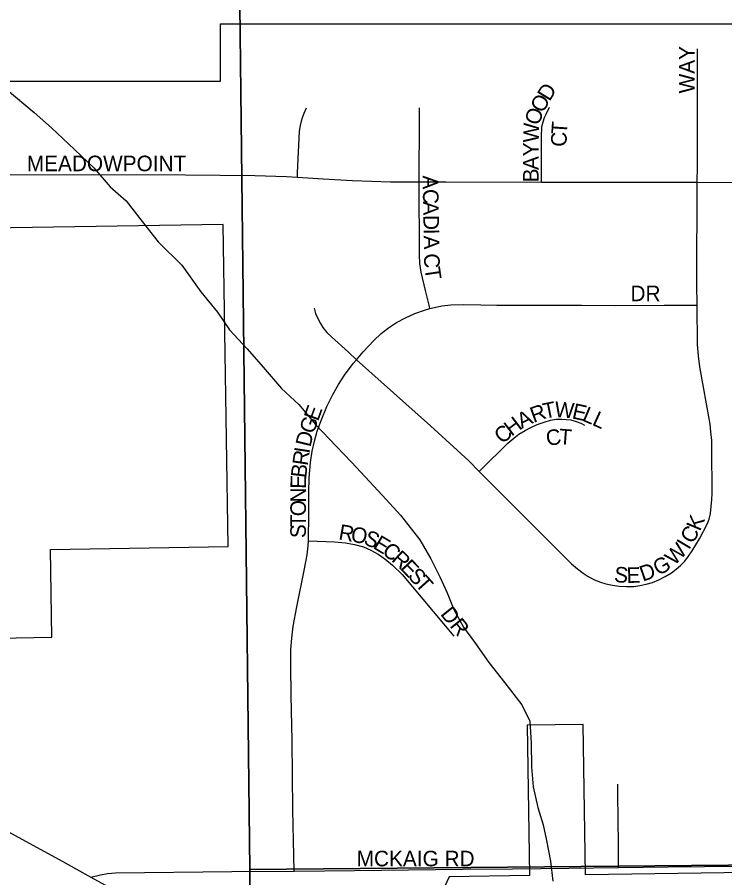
# Model space of a CAD drawing. Extents: x 0 to 680, y 0 to 440.
# Drawn here: x 433.41 to 441, y 330.74 to 339.97 of the extents above; entities that cross this region are included whole.
import ezdxf

# ---------------------------------------------------------------- set-up
doc = ezdxf.new("R2010")
doc.units = 0
for name, color, linetype in [('GM_X_City_Street', 7, 'Continuous'), ('GM_X_City_Street_Text', 7, 'Continuous'), ('GM_X_Corporation', 7, 'Continuous'), ('GM_X_County_Road', 7, 'Continuous'), ('GM_X_Minor_River', 7, 'Continuous'), ('GM_X_Section', 7, 'Continuous'), ('GM_X_State_Route', 7, 'Continuous')]:
    doc.layers.add(name, color=color, linetype=linetype)

msp = doc.modelspace()

# ---------------------------------------------------------------- linework, layer by layer
at = {"layer": 'GM_X_City_Street'}
for points in [[(440.7016, 338.1998), (440.7023, 338.3733), (440.7039, 339.1836), (440.7049, 339.6327)], [(436.411, 338.2539), (436.4132, 338.3002), (436.4344, 338.7505), (436.4431, 338.8091), (436.4639, 338.8851), (436.4846, 338.9427), (436.5098, 338.9997)], [(437.7185, 338.2041), (437.7182, 338.3199), (437.7207, 338.7769), (437.7219, 338.9986)], [(439.0301, 338.2029), (439.0301, 338.2146), (439.0305, 338.7275), (439.0325, 338.7598), (439.0343, 338.7904), (439.0409, 338.8235), (439.0486, 338.8508), (439.0639, 338.8941), (439.0792, 338.9298), (439.1171, 339.0069)], [(432.655, 338.2766), (432.6772, 338.2768), (433.3471, 338.2832), (435.2091, 338.2798), (435.9544, 338.2721), (436.2932, 338.2616), (436.411, 338.2539)], [(436.411, 338.2539), (436.6875, 338.2358), (437.0016, 338.2203), (437.4092, 338.2044), (437.7185, 338.2041)], [(437.8321, 336.8438), (437.8235, 336.88), (437.7854, 337.0397), (437.7382, 337.2373), (437.725, 337.328), (437.7204, 337.4221), (437.7185, 338.2041)], [(437.7185, 338.2041), (438.0055, 338.2038), (439.0301, 338.2029)], [(439.0301, 338.2029), (439.1397, 338.2028), (440.2238, 338.2008), (440.7016, 338.1998)], [(440.6995, 336.8821), (440.6977, 337.1031), (440.7016, 338.1998)], [(440.7016, 338.1998), (441.4396, 338.1982), (441.6928, 338.1889), (441.7558, 338.1827), (441.8128, 338.1712), (441.8745, 338.1537)], [(437.8321, 336.8438), (437.8828, 336.858), (437.9592, 336.873), (438.0585, 336.8837), (438.1909, 336.8884), (438.3775, 336.8844), (438.5524, 336.8817), (439.0009, 336.8805), (439.4609, 336.8806), (439.822, 336.8778), (440.3474, 336.8806), (440.5663, 336.8816), (440.6995, 336.8821)], [(438.3622, 335.0968), (439.3519, 334.1055), (439.4162, 334.0509), (439.4783, 334.0039), (439.5304, 333.9695), (439.5908, 333.9366), (439.6511, 333.913), (439.7204, 333.8904), (439.7903, 333.8776), (439.8634, 333.8669), (439.9409, 333.861), (440.0194, 333.8627), (440.0842, 333.871), (440.1518, 333.8856), (440.2208, 333.9064), (440.288, 333.9349), (440.3559, 333.9695), (440.4246, 334.0098), (440.4741, 334.0482), (440.5215, 334.0862), (440.5673, 334.1349), (440.608, 334.186), (440.648, 334.245), (440.7271, 334.3741), (440.8092, 334.5314), (440.8289, 334.5831), (440.8416, 334.6454), (440.852, 334.7217), (440.8573, 334.795), (440.8598, 334.8594), (440.8569, 335.3478), (440.8569, 335.4283), (440.8481, 335.521), (440.8409, 335.6058), (440.7284, 336.2204), (440.7133, 336.3383), (440.7032, 336.458), (440.6995, 336.8821)], [(436.5894, 336.8497), (436.6071, 336.7912), (436.6268, 336.7452), (436.6586, 336.6845), (436.6858, 336.6401), (436.7269, 336.5894), (436.7779, 336.5422), (436.9579, 336.3757), (437.0465, 336.2962)], [(437.0465, 336.2962), (437.1177, 336.3805), (437.2304, 336.5014), (437.3108, 336.5774), (437.3893, 336.6391), (437.4731, 336.6937), (437.5706, 336.7463), (437.6718, 336.7911), (437.7763, 336.828), (437.8321, 336.8438)], [(436.5289, 334.3524), (436.5318, 334.4055), (436.5344, 334.5908), (436.5353, 334.8758), (436.5382, 335.0295), (436.5535, 335.1941), (436.5705, 335.3143), (436.5934, 335.4225), (436.6235, 335.5289), (436.6647, 335.6431), (436.7287, 335.7953), (436.7912, 335.9242), (436.8517, 336.0296), (436.9183, 336.1311), (437.0111, 336.2544), (437.0465, 336.2962)], [(437.0465, 336.2962), (437.8381, 335.5856), (438.2499, 335.2093), (438.3622, 335.0968)], [(438.3622, 335.0968), (438.3817, 335.1161), (438.6689, 335.4008), (438.7323, 335.4542), (438.7883, 335.4969), (438.8546, 335.5368), (438.915, 335.5692), (438.9828, 335.6001), (439.0579, 335.6267), (439.1257, 335.6458), (439.1891, 335.6562), (439.2495, 335.6591), (439.3452, 335.6502), (439.4027, 335.634), (439.4515, 335.6137), (439.4903, 335.5934)], [(436.3759, 330.8081), (436.3621, 331.4654), (436.3544, 332.2099), (436.3453, 332.6914), (436.3403, 333.0092), (436.3425, 333.1851), (436.3503, 333.306), (436.3671, 333.4372), (436.4049, 333.6426), (436.489, 334.0499), (436.5145, 334.2), (436.5257, 334.297), (436.5289, 334.3524)], [(436.5289, 334.3524), (436.8076, 334.3412), (436.9275, 334.329), (437.0246, 334.312), (437.1198, 334.2866), (437.2007, 334.2533), (437.2768, 334.2102), (437.3487, 334.1601), (437.433, 334.0902), (437.5361, 333.9918), (438.0884, 333.3279)], [(439.8573, 330.8461), (439.8564, 330.9291), (439.8548, 331.0944), (439.8522, 331.361), (439.8495, 331.6323), (439.8484, 331.7399)], [(437.0245, 330.8133), (438.1818, 330.827)]]:
    msp.add_lwpolyline(points, dxfattribs=at)
at = {"layer": 'GM_X_Corporation'}
for points in [[(432.4035, 339.285), (435.5878, 339.2856), (435.5877, 339.8995), (444.4829, 339.9013), (449.0341, 339.9022)], [(432.4349, 333.2942), (433.7764, 333.3162), (433.7609, 334.2583), (435.6699, 334.2896), (435.6133, 337.7488), (432.4295, 337.6967)], [(445.5048, 330.6277), (445.5155, 330.7981), (444.5882, 330.7962), (444.0115, 330.788), (443.9901, 332.2896), (441.713, 332.2571), (441.7338, 330.7993), (439.5011, 330.7675), (439.478, 332.382), (438.8773, 332.3734), (438.9004, 330.7589), (438.0395, 330.7466), (437.2449, 329.0442)]]:
    msp.add_lwpolyline(points, dxfattribs=at)
at = {"layer": 'GM_X_County_Road'}
for points in [[(439.8573, 330.8461), (440.3898, 330.852), (441.554, 330.8648)], [(434.1965, 330.7436), (434.2979, 330.7671), (434.3735, 330.7824), (434.4594, 330.7893), (435.7089, 330.8026), (436.3759, 330.8081)], [(436.3759, 330.8081), (436.7018, 330.8107), (437.0245, 330.8133)], [(438.1818, 330.827), (438.7175, 330.8305)], [(438.7175, 330.8305), (439.0231, 330.8353), (439.3232, 330.8401)], [(439.3232, 330.8401), (439.8573, 330.8461)]]:
    msp.add_lwpolyline(points, dxfattribs=at)
at = {"layer": 'GM_X_Minor_River'}
msp.add_lwpolyline([(433.2973, 339.194), (433.5875, 338.9482), (433.7721, 338.7845), (433.9566, 338.6141), (434.2266, 338.3553), (434.4039, 338.1516), (434.5753, 338.0015), (434.7455, 337.7779), (434.9159, 337.5609), (435.1726, 337.309), (435.3752, 337.0246), (435.5522, 336.8075), (435.6829, 336.618), (435.8735, 336.414), (436.0442, 336.2171), (436.241, 335.9863), (436.4256, 335.8159), (436.6093, 335.5987), (436.8262, 335.3676), (436.9906, 335.1975), (437.1878, 334.9868), (437.3653, 334.7965), (437.5163, 334.6267), (437.726, 334.3622), (437.843, 334.1595), (437.9401, 333.9639), (438.0176, 333.7953), (438.0882, 333.6135), (438.192, 333.4244), (438.3229, 333.2482), (438.4667, 333.0451), (438.6371, 332.8281), (438.8205, 332.5909), (438.9045, 332.4155), (438.9206, 332.1811), (438.9231, 331.9268), (438.9396, 331.7124), (438.9894, 331.4908), (439.0465, 331.3025), (439.0838, 331.1346), (439.1269, 330.9131), (439.1501, 330.6986)], dxfattribs=at)
at = {"layer": 'GM_X_Section'}
for points in [[(453.5154, 348.7506), (453.6769, 330.9853), (435.9013, 330.8241), (435.7026, 347.83), (435.7081, 348.4306)], [(435.7026, 347.83), (435.9013, 330.8241), (435.9069, 330.1031), (418.3618, 330.3155), (418.3416, 347.8986)], [(453.6769, 330.9853), (453.7725, 312.8943), (435.9077, 312.881), (435.9069, 330.1031), (435.9013, 330.8241)]]:
    msp.add_lwpolyline(points, close=True, dxfattribs=at)
at = {"layer": 'GM_X_State_Route'}
for points in [[(432.7098, 331.5498), (433.1173, 331.3324), (433.4933, 331.1297), (433.8947, 330.9103), (434.0423, 330.8288)], [(434.0423, 330.8288), (434.1965, 330.7436)], [(434.1965, 330.7436), (434.3466, 330.6597), (434.6114, 330.5195), (434.7766, 330.4317)]]:
    msp.add_lwpolyline(points, dxfattribs=at)

# ---------------------------------------------------------------- texts
at = {"layer": 'GM_X_City_Street_Text'}
for s, height, rotation, p in [('WAY', 0.16689, 90, (440.673, 339.1543)), ('D', 0.1669, 58.31661, (439.116, 339.0608)), ('O', 0.1669, 60.39338, (439.0442, 338.9345)), ('O', 0.1669, 72.34609, (439.0034, 338.803)), ('W', 0.1669, 88.30147, (438.9998, 338.6243)), ('T', 0.1669, 86.00781, (439.3009, 338.7106)), ('C', 0.1669, 89.80569, (439.3005, 338.5813)), ('Y', 0.1669, 89.8578, (438.9995, 338.4786)), ('MEADOWPOINT', 0.166893, 0.00001, (433.508, 338.3192)), ('A', 0.1669, 89.84697, (438.9991, 338.3317)), ('A', 0.1669, 271.04919, (437.7544, 338.2733)), ('B', 0.1669, 89.85426, (438.9987, 338.1996)), ('C', 0.1669, 271.04428, (437.7571, 338.1265)), ('A', 0.1669, 271.02733, (437.7595, 337.9943)), ('D', 0.1669, 271.0521, (437.7622, 337.8474)), ('I', 0.1669, 271.05928, (437.7649, 337.7005)), ('A', 0.1669, 271.02733, (437.7662, 337.6271)), ('C', 0.1669, 271.04428, (437.7697, 337.436)), ('T', 0.1669, 278.4014, (437.774, 337.2806)), ('DR', 0.16689, 0.00001, (439.9847, 336.9239)), ('E', 0.1669, 70.00989, (436.6325, 335.6279)), ('R', 0.1669, 20.23205, (438.945, 335.6166)), ('T', 0.1669, 11.19204, (439.0623, 335.6605)), ('W', 0.1669, 355.26987, (439.1654, 335.6826)), ('E', 0.1669, 347.60753, (439.3498, 335.6677)), ('L', 0.1669, 337.01662, (439.4568, 335.645)), ('G', 0.1669, 70.41085, (436.5833, 335.4898)), ('H', 0.1669, 37.23274, (438.7081, 335.4684)), ('A', 0.1669, 26.55528, (438.8181, 335.5529)), ('L', 0.1669, 335.54926, (439.5639, 335.5996)), ('C', 0.1669, 40.01389, (438.6086, 335.3847)), ('D', 0.1669, 76.45666, (436.5502, 335.3515)), ('C', 0.1669, 10.10504, (439.0936, 335.3673)), ('T', 0.1669, 355.40429, (439.2124, 335.3899)), ('R', 0.1669, 81.44401, (436.5203, 335.1519)), ('I', 0.1669, 81.35684, (436.5399, 335.2825)), ('B', 0.1669, 83.32989, (436.5051, 335.0221)), ('E', 0.1669, 88.6068, (436.5025, 334.9086)), ('N', 0.1669, 89.93441, (436.5024, 334.7628)), ('O', 0.1669, 89.93441, (436.5022, 334.616)), ('T', 0.1669, 89.93222, (436.5021, 334.4985)), ('K', 0.1669, 67.26989, (440.7303, 334.4476)), ('S', 0.1669, 89.94534, (436.502, 334.3811)), ('R', 0.1669, 349.87106, (436.8458, 334.3683)), ('O', 0.1669, 349.87302, (436.976, 334.345)), ('C', 0.1669, 58.97718, (440.6503, 334.3108)), ('S', 0.1669, 336.65071, (437.1108, 334.3221)), ('E', 0.1669, 328.75045, (437.2133, 334.2784)), ('C', 0.1669, 322.07603, (437.3095, 334.2203)), ('W', 0.1669, 46.36704, (440.4564, 334.0779)), ('I', 0.1669, 58.9281, (440.6123, 334.2477)), ('R', 0.1669, 317.6283, (437.4111, 334.1413)), ('E', 0.1669, 313.55101, (437.5066, 334.0544)), ('D', 0.1669, 19.24631, (440.1172, 333.9125)), ('G', 0.1669, 28.76338, (440.2835, 333.9731)), ('S', 0.1669, 312.23695, (437.5868, 333.97)), ('S', 0.1669, 354.11541, (439.8041, 333.912)), ('E', 0.1669, 1.61406, (439.9448, 333.899)), ('T', 0.1669, 311.98519, (437.6657, 333.8831)), ('DR', 0.16689, 308.66337, (437.9384, 333.5636)), ('MCKAIG RD', 0.16689, 0.00001, (437.0474, 330.8584))]:
    msp.add_text(s, height=height, rotation=rotation, dxfattribs=at).set_placement(p)

doc.saveas('drawing.dxf')
